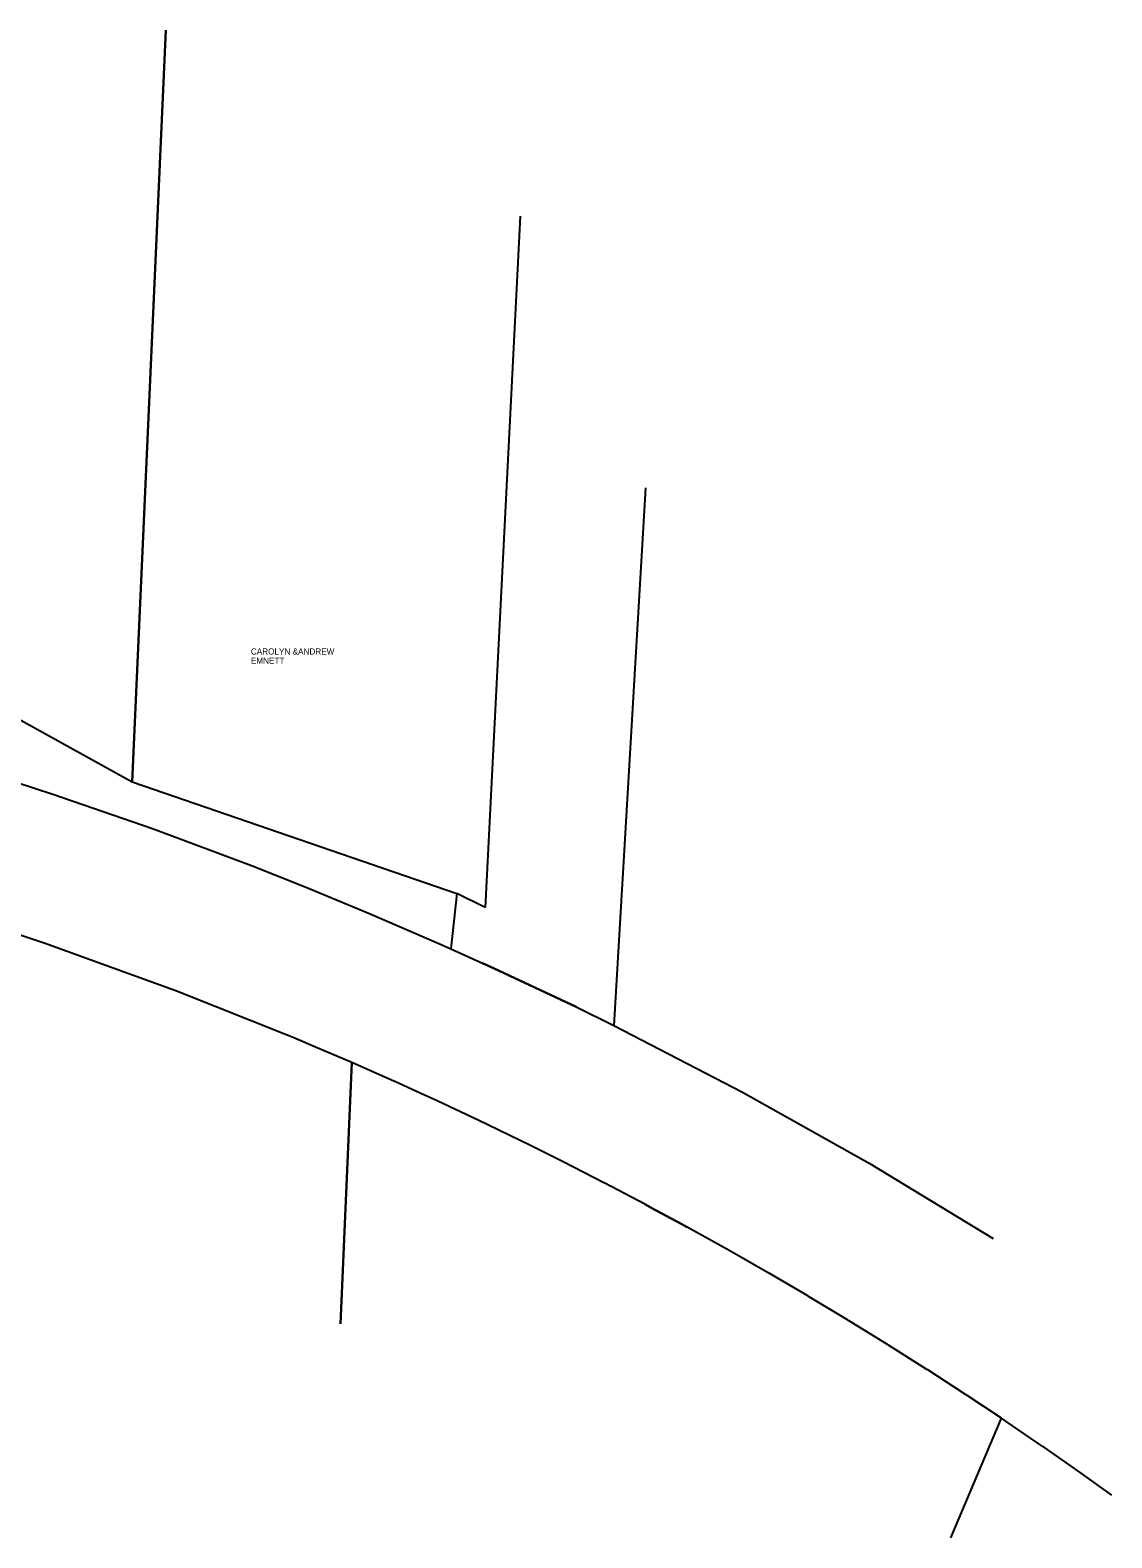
# Model space of a CAD drawing. Extents: x 2231872 to 2232859, y 415364 to 416122.
# Drawn here: x 2232363 to 2232859, y 415364 to 416055 of the extents above; entities that cross this region are included whole.
import ezdxf

# ---------------------------------------------------------------- set-up
doc = ezdxf.new("R2010")
doc.units = 0
doc.layers.add('Default', color=7, linetype='Continuous')

msp = doc.modelspace()

# ---------------------------------------------------------------- linework, layer by layer
at = {"layer": 'Default'}
for p, q in [((2232409.99, 415710.01), (2232425.47, 416054.52)), ((2232425.47, 416054.52), (2232409.99, 415710.01)), ((2232587.91, 415969.22), (2232571.99, 415652.49)), ((2232587.91, 415969.22), (2232571.99, 415652.49)), ((2232645.5, 415844.85), (2232630.89, 415598.43)), ((2232206.99, 415822.32), (2232409.99, 415710.01)), ((2232356.85, 415709.92), (2232373.6, 415704.45)), ((2232409.99, 415710.01), (2232558.97, 415658.88)), ((2232558.97, 415658.88), (2232556.13, 415633.53)), ((2232571.99, 415652.49), (2232558.97, 415658.88)), ((2232513.76, 415651.9), (2232519.26, 415649.58)), ((2232369.67, 415636.13), (2232340.77, 415645.76)), ((2232519.26, 415649.58), (2232551.78, 415635.47)), ((2232431.35, 415613.81), (2232369.67, 415636.13)), ((2232551.78, 415635.47), (2232556.13, 415633.53)), ((2232556.13, 415633.53), (2232570.7, 415626.99)), ((2232570.7, 415626.99), (2232576.03, 415624.56)), ((2232576.03, 415624.56), (2232613.59, 415606.9)), ((2232431.55, 415613.74), (2232431.35, 415613.81)), ((2232480.42, 415594.29), (2232431.55, 415613.74)), ((2232613.59, 415606.9), (2232630.89, 415598.43)), ((2232484.23, 415592.71), (2232480.42, 415594.29)), ((2232495.25, 415588.07), (2232484.23, 415592.71)), ((2232510.73, 415581.43), (2232495.25, 415588.07)), ((2232510.73, 415581.43), (2232505.64, 415461.67)), ((2232505.64, 415461.67), (2232510.73, 415581.43)), ((2232530.28, 415572.79), (2232510.73, 415581.43)), ((2232530.52, 415572.68), (2232530.28, 415572.79)), ((2232542.38, 415567.3), (2232530.52, 415572.68)), ((2232549.99, 415563.81), (2232542.38, 415567.3)), ((2232569.04, 415554.87), (2232549.99, 415563.81)), ((2232573.22, 415552.88), (2232569.04, 415554.87)), ((2232588.31, 415545.56), (2232573.22, 415552.88)), ((2232592.06, 415543.72), (2232588.31, 415545.56)), ((2232607.45, 415536.05), (2232592.06, 415543.72)), ((2232607.73, 415535.9), (2232607.45, 415536.05)), ((2232626.41, 415526.35), (2232607.73, 415535.9)), ((2232626.57, 415526.27), (2232626.41, 415526.35)), ((2232645.39, 415516.37), (2232626.57, 415526.27)), ((2232648.42, 415514.74), (2232645.39, 415516.37)), ((2232661.8, 415507.51), (2232648.42, 415514.74)), ((2232664.48, 415506.05), (2232661.8, 415507.51)), ((2232682.77, 415495.89), (2232664.48, 415506.05)), ((2232683.06, 415495.73), (2232682.77, 415495.89)), ((2232701.43, 415485.25), (2232683.06, 415495.73)), ((2232701.84, 415485.01), (2232701.43, 415485.25)), ((2232719.87, 415474.45), (2232701.84, 415485.01)), ((2232720.21, 415474.25), (2232719.87, 415474.45)), ((2232738.06, 415463.53), (2232720.21, 415474.25)), ((2232738.54, 415463.23), (2232738.06, 415463.53)), ((2232756.38, 415452.23), (2232738.54, 415463.23)), ((2232756.91, 415451.9), (2232756.38, 415452.23)), ((2232774.44, 415440.81), (2232756.91, 415451.9)), ((2232774.89, 415440.53), (2232774.44, 415440.81)), ((2232792.21, 415429.29), (2232774.89, 415440.53)), ((2232792.89, 415428.85), (2232792.21, 415429.29)), ((2232808.64, 415418.39), (2232792.89, 415428.85)), ((2232785.48, 415363.6), (2232808.64, 415418.39)), ((2232810.78, 415416.95), (2232808.64, 415418.39)), ((2232827.83, 415405.33), (2232810.78, 415416.95)), ((2232828.35, 415404.98), (2232827.83, 415405.33)), ((2232845.26, 415393.17), (2232828.35, 415404.98)), ((2232845.82, 415392.78), (2232845.26, 415393.17)), ((2232859.31, 415383.15), (2232845.82, 415392.78))]:
    msp.add_line(p, q, dxfattribs=at)
for points in [[(2232373.6, 415704.45), (2232419.38, 415688.63), (2232464.76, 415671.68), (2232489.33, 415661.95), (2232513.76, 415651.9)], [(2232613.59, 415606.9), (2232576.03, 415624.56), (2232570.7, 415626.99)], [(2232630.89, 415598.43), (2232689.97, 415567.88), (2232747.97, 415535.33), (2232804.82, 415500.81)], [(2232645.39, 415516.37), (2232648.42, 415514.74), (2232661.8, 415507.51), (2232664.48, 415506.05)]]:
    msp.add_lwpolyline(points, dxfattribs=at)

# ---------------------------------------------------------------- texts
for s, p in [('CAROLYN &ANDREW', (2232464.49, 415768.38)), ('EMNETT', (2232464.49, 415764.18))]:
    msp.add_text(s, height=2.8, dxfattribs=at).set_placement(p)

doc.saveas('drawing.dxf')
